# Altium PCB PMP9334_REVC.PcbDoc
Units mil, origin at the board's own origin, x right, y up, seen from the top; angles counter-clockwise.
Board outline 4400 x 1100 mil, 4 copper layers (Top Layer, Mid-Layer 1, Mid-Layer 2, Bottom Layer), stack 61.8 mil thick; 57 components, 29 nets, 127 pads, 87 vias.
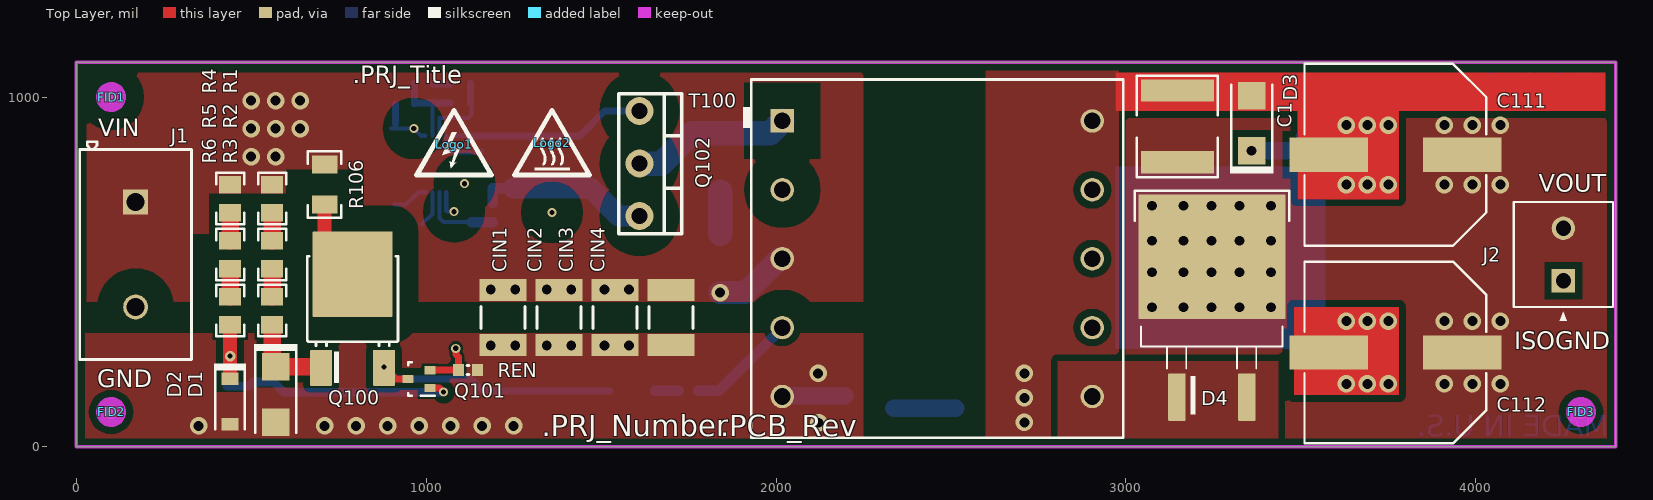
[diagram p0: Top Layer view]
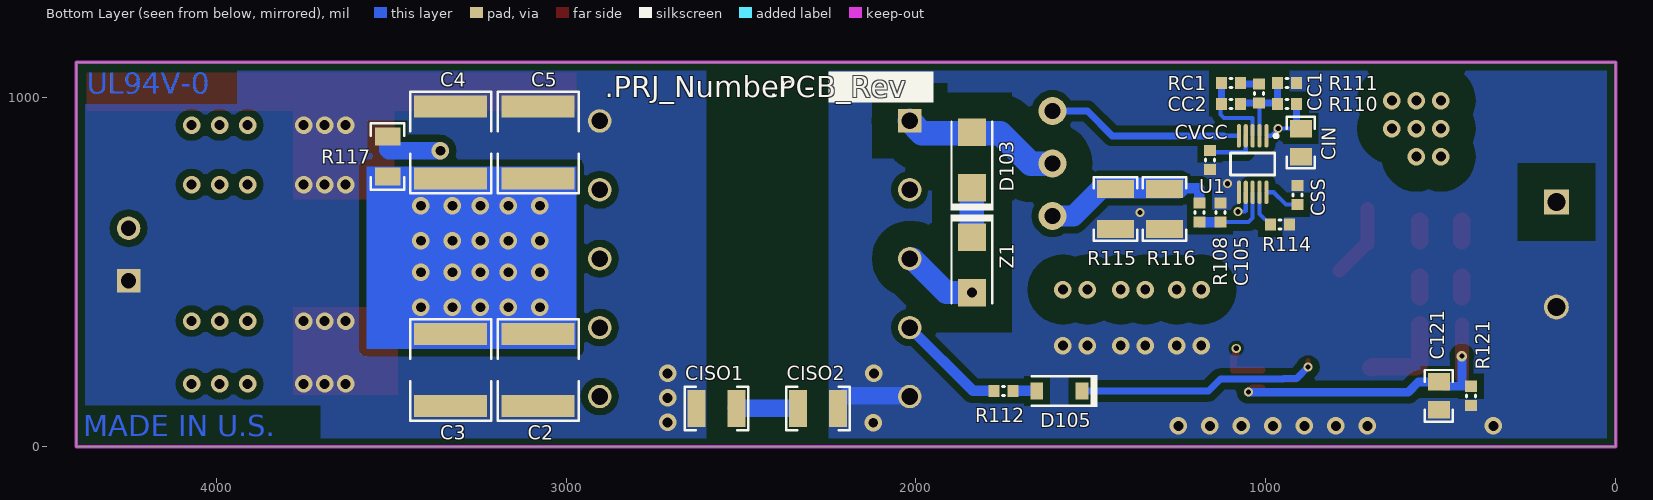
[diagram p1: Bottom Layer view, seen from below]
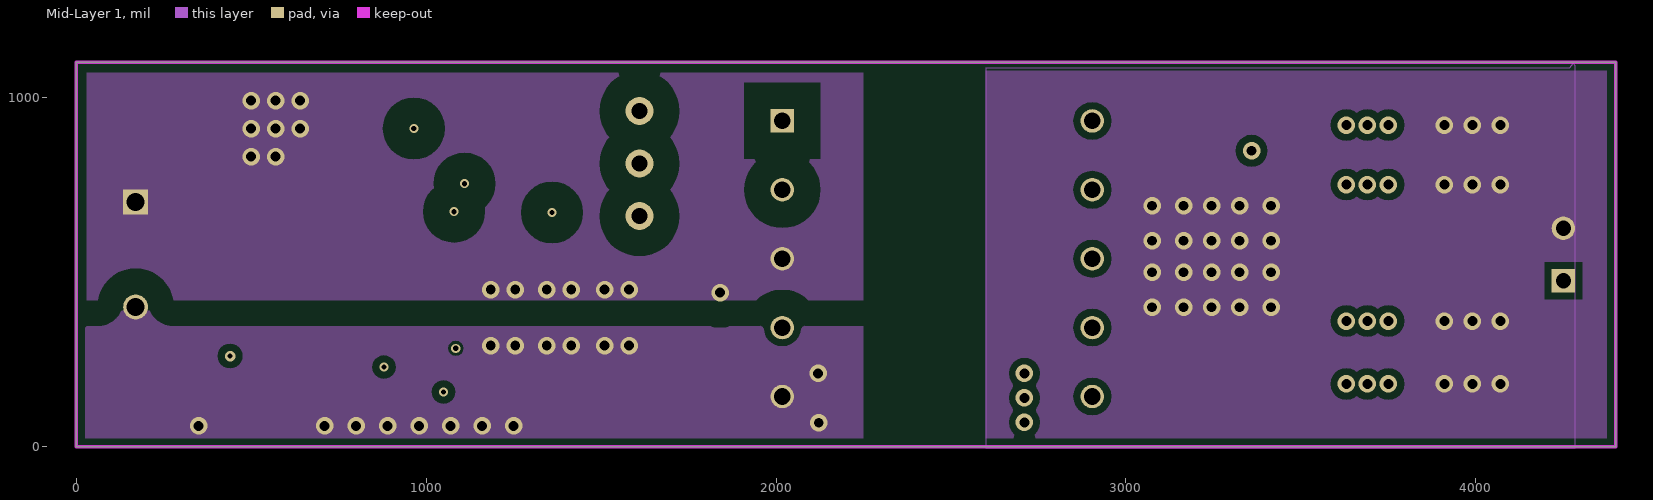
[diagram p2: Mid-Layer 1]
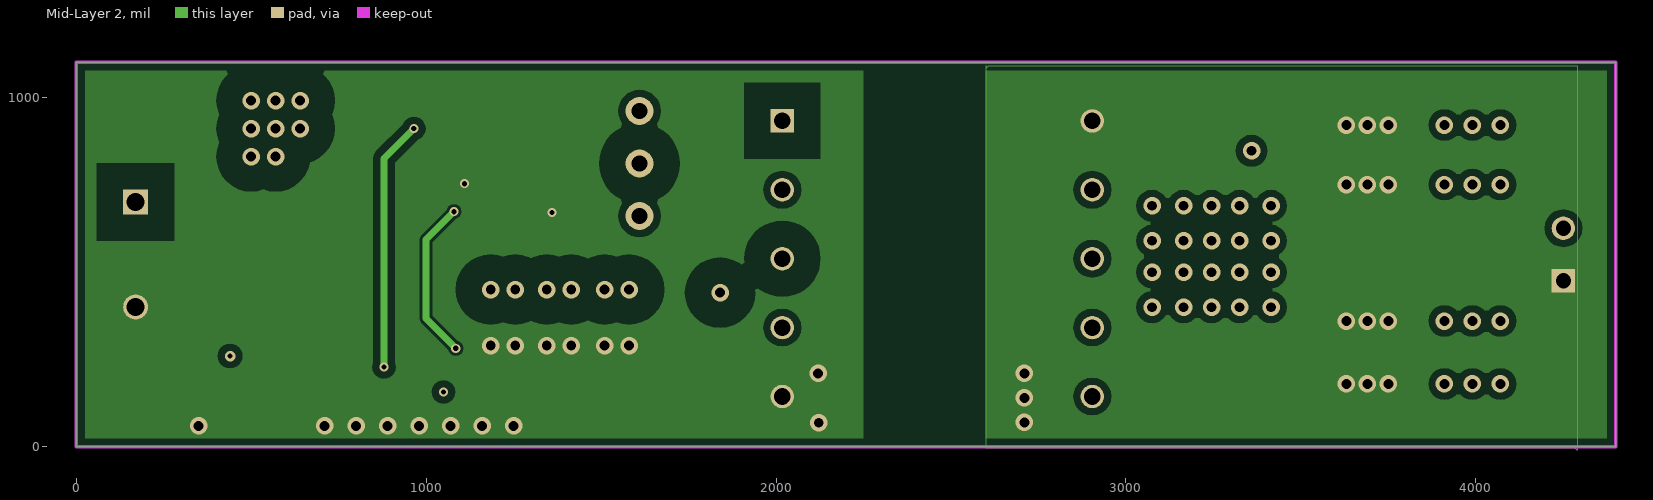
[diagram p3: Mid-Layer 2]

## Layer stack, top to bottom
Top Solder: solder mask 0.4, Solder Resist, Dk 3.5
Top Layer: signal copper 1.4
Dielectric1: prepreg 12.6, FR-4, Dk 4.2
Mid-Layer 1: signal copper 1.4
Dielectric2: core 31, FR-4, Dk 4.2
Mid-Layer 2: signal copper 1.4
Dielectric3: prepreg 12.6, FR-4, Dk 4.2
Bottom Layer: signal copper 1.4
Bottom Solder: solder mask 0.4, Solder Resist, Dk 3.5

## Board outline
0,0 4400,0 4400,1100 0,1100

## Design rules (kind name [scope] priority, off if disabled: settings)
AcuteAngle [All] p1: minimum=4.50000000000000E+0001 checktracksonly=FALSE
AssemblyTestPointUsage [All] p1: valid=2
Clearance Clearance_1206 [HasFootprint('1206') vs HasFootprint('1206')] p1: gap=60
Clearance Clearance_Keepouts [((IsTrack Or IsArc) And Not InPoly) And IsFree and IsKeepOut vs ((IsTrack Or IsArc) And Not InPoly) And IsFree and IsKeepOut] p2: gap=25
Clearance Clearance_SYNC [InNet('SYNC') vs InNet('CS') or InNet('SS')] p3: gap=7.8
Clearance Clearance_UVLO [InNet('UVLO') vs InNet('CS') or InNet('GND')] p4: gap=7.8
Clearance Clearance_CS [InNet('CS') vs InNet('UVLO') or InNet('SYNC')] p5: gap=7.8
Clearance Clearance_FB [InNet('FB') vs InNet('VIN IC') or InNet('COMP')] p6: gap=7.8
Clearance Clearance_COMP [InNet('COMP') vs InNet('FB') or InNet('VCC')] p7: gap=7.8
Clearance Clearance_VCC [InNet('VCC') vs InNet('COMP') or InNet('OUT')] p8: gap=7.8
Clearance Clearance_MUB10A-N [HasFootprint('MUB10A_N') vs HasFootprint('MUB10A_N')] p9: gap=8
Clearance Clearance_R4 [InNet('NetR4_1') vs InNet('VIN HV')] p10: gap=30
Clearance Clearance_R1 [InNet('VIN HV') vs InNet('NetR1_1')] p11: gap=30
Clearance Clearance_ISO [InNet('ISO') vs InNet('GND') or InNet('ISO GND')] p12: gap=60
Clearance Clearance_NMOS_DRAIN [InNet('VIN HV') vs InNet('NMOS DRAIN')] p13: gap=75
Clearance Clearance_TO220 [HasFootprint('TO220-3_A') vs HasFootprint('TO220-3_A')] p14: gap=70
Clearance Clearance_HV_KeepOut [InNetClass('HV') vs IsKeepOut] p15: gap=25
Clearance Clearance_HV [InNetClass('HV')] p16: gap=75
Clearance Clearance_Poly [InPolygon] p17: gap=20
Clearance Clearance_BoardEdge_MountingHoles [OnCopper and InComponentClass('Mounting Holes') vs IsKeepOut] p18: gap=40
Clearance Clearance_BoardEdge_Poly [OnCopper and (InPoly or IsRegion) vs IsKeepOut] p19: gap=25
Clearance Clearance_BoardEdge [OnCopper and Not InComponentClass('Logo') and not InComponentClass('FiducialMark') and not InRegion(1000,500,4000,800) and Not IsKeepout vs IsKeepOut] p20: gap=25
Clearance [All] p21: gap=7.87
ComponentClearance ComponentClearance_MountingHoles_FiducialMarks [InComponentClass('Mounting Holes') vs InComponentClass('FiducialMark')] p1: gap=50 collisioncheckmode=3 verticalgap=10 showdistances=FALSE
ComponentClearance ComponentClearance_Shunt [InComponentClass('Header') vs InComponentClass('Shunt')] p2: gap=0 collisioncheckmode=3 verticalgap=0 showdistances=FALSE
ComponentClearance ComponentClearance_Logo [InComponentClass('Logo')] p3: gap=50 collisioncheckmode=3 verticalgap=10 showdistances=FALSE
ComponentClearance ComponentClearance_ScrewToNut [(HasFootprint('NY PMS 440 0025 PH')) vs (HasFootprint('Keystone_1902C'))] p4: gap=5 collisioncheckmode=3 verticalgap=10 showdistances=FALSE
ComponentClearance ComponentClearance_MountingHoles [InComponentClass('Mounting Holes')] p5: gap=250 collisioncheckmode=3 verticalgap=100000 showdistances=FALSE
ComponentClearance ComponentClearance_SmallPassives [HasFootprint('0201*') or HasFootprint('0402*') or HasFootprint('0508') or HasFootprint('0603*') or HasFootprint('0612') or HasFootprint('0805*') or HasFootprint('0815*') or HasFootprint('0830*') or HasFootprint('1206*') or HasFootprint('1210*') or HasFootprint('1808*') or HasFootprint('1812*') or HasFootprint('1825*') or HasFootprint('2010*') or HasFootprint('2220*') or HasFootprint('2225*') or HasFootprint('2512*') or HasFootprint('2728*') or HasFootprint('3518*') vs HasFootprint('0201*') or HasFootprint('0402*') or HasFootprint('0508') or HasFootprint('0603*') or HasFootprint('0612') or HasFootprint('0805*') or HasFootprint('0815*') or HasFootprint('0830*') or HasFootprint('1206*') or HasFootprint('1210*') or HasFootprint('1808*') or HasFootprint('1812*') or HasFootprint('1825*') or HasFootprint('2010*') or HasFootprint('2220*') or HasFootprint('2225*') or HasFootprint('2512*') or HasFootprint('2728*') or HasFootprint('3518*')] p6: gap=20 collisioncheckmode=3 verticalgap=10 showdistances=FALSE
ComponentClearance ComponentClearance_THtoSMT [IsThruComponent vs IsSMTComponent] p7: gap=50 collisioncheckmode=3 verticalgap=30 showdistances=FALSE
ComponentClearance ComponentClearance_THtoTH [IsThruComponent vs IsThruComponent] p8: gap=50 collisioncheckmode=3 verticalgap=30 showdistances=FALSE
ComponentClearance [All] p9: gap=40 collisioncheckmode=3 verticalgap=10 showdistances=FALSE
DiffPairsRouting [All] p1: maxlimit=100 minlimit=10 mostfreqgap=10 toplayer_minwidth=15 toplayer_maxwidth=15 toplayer_prefwidth=15 midlayer1_minwidth=15 midlayer1_maxwidth=15 midlayer1_prefwidth=15 midlayer2_minwidth=15 midlayer2_maxwidth=15 midlayer2_prefwidth=15 bottomlayer_minwidth=15 bottomlayer_maxwidth=15 bottomlayer_prefwidth=15 maxuncoupledlength=1000
FabricationTestPointUsage TestPointUsage [All] p1: valid=2 allowmultiple=FALSE
FabricationTestpoint Testpoint [All] p1: side=3 testpointundercomponent=TRUE minsize=40 maxsize=100 preferedsize=60 minholesize=0 maxholesize=40 preferedholesize=32 testpointgrid=1 allowsidetop=TRUE allowsidebottom=TRUE usegrid=TRUE gridtolerance=0.01
FanoutControl Fanout_LCC [IsLCC] p1: bgadir=Out bgaviamode=Centered fanoutstyle=Auto fanoutdirection=Alternating viagrid=1 // Fanout_LCC (Default Rule)
FanoutControl Fanout_BGA [IsBGA] p2: bgadir=Out bgaviamode=Centered fanoutstyle=Auto fanoutdirection=Alternating viagrid=1 // Fanout_BGA (Default Rule)
FanoutControl Fanout_Default [All] p4: bgadir=Out bgaviamode=Centered fanoutstyle=Auto fanoutdirection=Alternating viagrid=1 // Fanout_Default (Default Rule)
FanoutControl Fanout_Small [(CompPinCount < 5)] p5: bgadir=Out bgaviamode=Centered fanoutstyle=Auto fanoutdirection=OutThenIn viagrid=1 // Fanout_Small (Default Rule)
Height [All] p1: minheight=0 maxheight=1500 prefheight=500
HoleSize [All] p1: absolutevalues=TRUE maxlimit=251 minlimit=8 maxpercent=80.000 minpercent=20.000
MinimumAnnularRing MinimumAnnularRing_ThermalPadVias [IsVia and InAnyComponent] p1: minimumring=5.91
MinimumAnnularRing [All] p2: minimumring=5
MinimumSolderMaskSliver MinimumSolderMaskSliver_Logo [InComponentClass('Logo') vs InComponentClass('Logo')] p1: minsoldermaskwidth=0.7
MinimumSolderMaskSliver [All] p2: minsoldermaskwidth=3.94
PlaneConnect [All] p1: planeconnectstyle=Direct reliefexpansion=10 reliefentries=4 reliefconductorwidth=10 reliefairgap=10
PolygonConnect [All] p1: connectstyle=Direct reliefconductorwidth=10 reliefentries=4 polygonreliefangle="90 Angle" airgapwidth=10
RoutingVias ThermalPadVias [IsVia and InAnyComponent] p1: holewidth=7.87 width=19.68 viastyle="Through Hole" minholewidth=7.87 minwidth=19.68 maxholewidth=12.99 maxwidth=23.62
RoutingVias [All] p2: holewidth=16 width=34 viastyle="Through Hole" minholewidth=7.87 minwidth=20 maxholewidth=40 maxwidth=65
SMDToCorner [All] p1: distance=4000
SilkToBoardRegionClearance [Not ((IsComment or IsDesignator) And (Hide <> 'False')) and not InRegion(1000,500,4000,800)] p1:
SilkToSilkClearance SilkToSilkClearance_Pb-FreeLogo [(HasFootprint('Pb-Free_Overlay_Medium') OR HasFootprint('Pb-Free_Overlay_Small')) vs (HasFootprint('Pb-Free_Overlay_Medium') OR HasFootprint('Pb-Free_Overlay_Small'))] p1: silktosilkclearance=0
SilkToSilkClearance [All] p2: silktosilkclearance=4
SilkToSolderMaskClearance SilkToComonentPadClearance [IsPad and InAnycomponent] p1: minsilkscreentomaskgap=5 clearancetoexposedcopper=TRUE
SilkToSolderMaskClearance "Silk to Solder Mask Opening" [All] p2: minsilkscreentomaskgap=4 clearancetoexposedcopper=FALSE
SilkToSolderMaskClearance SilkscreenOverComponentPads [IsPad] p3: minsilkscreentomaskgap=5 clearancetoexposedcopper=TRUE
SolderMaskExpansion [All] p1: expansion=1.97
UnpouredPolygon [All] p1: allowunpoured=FALSE
Width [All] p1: maxlimit=100 minlimit=6 preferedwidth=10 checkconnectedcopper=TRUE
13 further rules are at their usual default settings.

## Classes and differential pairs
component class FiducialMark: FID1 FID2 FID3
net class HV: "NMOS DRAIN" "PRI SW" "SNUB SW" "VIN HV"

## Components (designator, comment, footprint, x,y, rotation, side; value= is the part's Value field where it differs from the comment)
C1 "C5750X7S2A106M230KB" 2220_280 3147,916 r90 top
C2 "DNP" 2220_280 3080,220 r270 bottom
C3 "DNP" 2220_280 3330,220 r270 bottom
C4 "DNP" 2220_280 3330,870 r90 bottom
C5 "DNP" 2220_280 3080,870 r90 bottom
C105 "C0603C681K5RACTU" 0603L 1130,670 r90 bottom
C111 "EMVY350ATR471MKE0S" CAPSMT_62_KE0 3770,835 r180 top
C112 "EMVY350ATR471MKE0S" CAPSMT_62_KE0 3770,270 r180 top
C121 "GRM21BR71E334KA01L" 0805_HV 506,146 r270 bottom
CC1 "C0603C474K4RACTU" 0603L 1020,1010 r90 bottom
CC2 "C0603C331K5RACTU" 0603L 1100,980 r0 bottom
CIN "C2012X5R1E106K125AB" 0805_HV 900,870 r270 bottom
CIN1 "C1812V473KDRACTU" 1812 1220,370 r270 top
CIN2 "C1812V473KDRACTU" 1812 1380,370 r270 top
CIN3 "C1812V473KDRACTU" 1812 1540,370 r270 top
CIN4 "C1812V473KDRACTU" 1812 1700,370 r270 top
CISO1 "VJ1210A102JXGAT5Z" 1210 2570,110 r180 bottom
CISO2 "VJ1210A102JXGAT5Z" 1210 2280,110 r180 bottom
CSS "C0603C474K4RACTU" 0603L 910,720 r90 bottom
CVCC "GRM188R61E105KA12D" 0603L 1160,820 r270 bottom
D1 "CMZ5929B TR13" SMA 570,150 r270 top
D2 "MMSZ5231B-7-F" SOD-123 440,130 r270 top
D3 "CMZ5931B LEAD FREE" SMA 3359,925 r90 top
D4 "MBRB20200CTT4G" DDPAK 3245.55,388.31 r90 top
D103 "DNP" SMA 1840,820 r90 bottom
D105 "BAV21W-7-F" SOD-123 1590,160 r0 bottom
FID1 "Fiducial" Fiducial10-20 100,1000 r0 top
FID2 "Fiducial" Fiducial10-20 100,100 r0 top
FID3 "Fiducial" Fiducial10-20 4300,100 r0 top
J1 "1707027" Phoenix_1707027 170,550 r270 top
J2 "1727010" PhoenixConact_1727010 4250,550 r90 top
Logo1 "DANGER HIGH VOLTAGE" IEC_HighVoltage_Small 1080,865 r0 top
Logo2 "CAUTION HOT SURFACE" IEC_HotSurface_Small 1360,870 r0 top
Q100 "FQD2N100TM" DPAK 790,360 r90 top
Q101 "CMST2222A TR" SOT-323 979.32,194 r180 top
Q102 "STP8NK100Z" TO220-3_A 1610,810 r0 top
R1 "CRCW0805200KJNEA" 0805_HV 560,710 r90 top
R2 "CRCW0805200KJNEA" 0805_HV 560,550 r90 top
R3 "CRCW0805200KJNEA" 0805_HV 560,390 r90 top
R4 "CRCW08051M00JNEA" 0805_HV 440,710 r90 top
R5 "CRCW08051M00JNEA" 0805_HV 440,550 r90 top
R6 "CRCW08051M00JNEA" 0805_HV 440,390 r90 top
R106 "CRCW12064K99FKEA" 1206 710,750 r90 top
R108 "CRCW0603499RFKEA" 0603L 1190,670 r90 bottom
R110 "RG1608P-1872-B-T5" 0603L 940,980 r180 bottom
R111 "CRCW06031K50FKEA" 0603L 940,1040 r0 bottom
R112 "CRCW060316R0JNEA" 0603L 1750,160 r180 bottom
R114 "CRCW0603215KFKEA" 0603L 960,635.5 r0 bottom
R115 "MCR25JZHFLR510" 1210 1430,680 r90 bottom
R116 "MCR25JZHFLR510" 1210 1290,680 r90 bottom
R117 "CRCW1206100RFKEA" 1206 3510,830 r270 bottom
R121 "RC0603FR-07300KL" 0603L 414,146 r90 bottom
RC1 "CRCW06031K87FKEA" 0603L 1100,1040 r180 bottom
REN "RC0603FR-07300KL" 0603L 1120,220 r180 top
T100 "G094215LF" GCI_G094215LF 2461,538 r0 top locked
U1 "LM5022MM" MUB10A_N 1038,808.5 r270 bottom
Z1 "DNP" SMA 1840,520 r270 bottom

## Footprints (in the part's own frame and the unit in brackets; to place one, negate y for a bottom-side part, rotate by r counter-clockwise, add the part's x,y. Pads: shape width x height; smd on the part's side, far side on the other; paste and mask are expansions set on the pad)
0603L [mm] "0603 from SM-752 data"
  rect 0.8x0.85 smd: 1(-0.7,0) 2(0.7,0)
  silkscreen extent -0.07,-0.33 0.07,0.33, body extent -0.87,-0.47 0.87,0.47, height 0.85
0805_HV [mil] "0805 with 30mil clearance between pads"
  rect 50x63 smd: 1(-40,0) 2(40,0)
  silkscreen extent -74,-40 74,40, body extent -43,-29 43,29, height 43
1206 [mm] "1206 from SM-752 data"
  rect 1.3x1.85 smd: 1(-1.45,0) 2(1.45,0)
  silkscreen extent -2.4,-1.21 2.4,1.21, body extent -1.7,-0.9 1.7,0.9, height 1.35
1210 [mm] "1210 from SM-752 data"
  rect 1.3x2.7 smd: 1(-1.45,0) 2(1.45,0)
  silkscreen extent -2.32,-1.57 2.32,1.57, body extent -1.7,-1.35 1.7,1.35, height 1.35
1812 [mm]
  rect 1.6x3.4 smd: 1(-2,0) 2(2,0)
  silkscreen extent -0.8,-1.6 0.8,1.6, body extent -2.4,-1.7 2.4,1.7, height 1.35
2220_280 [mm] "Chip Capacitor, Body 5.7x5.0mm, IPC Medium Density"
  rect 1.6x5.3 smd: 1(-2.6,0) 2(2.6,0)
  silkscreen extent -3.69,-2.94 3.69,2.94, body extent -2.95,-2.62 2.95,2.62, height 2.8
CAPSMT_62_KE0 [mm] "12.5 x 13.5mm:  Chemi-Con KE0"
  rect 5.7x2.5 smd: 1(-4.85,0) 2(4.85,0)
  silkscreen extent -6.6,-6.6 6.6,6.6, body extent -6.6,-6.6 6.6,6.6, height 14
DDPAK [mil] "D2-PAK, 3-Pads, Body 9.7x10.4mm (max), TO-263AB, using Vishay Silionix recommended pad sizes"
  rrect8% 135x49.49 smd: 1(-246.06,100) 3(-246.06,-100)
  rrect1% 355x420 smd paste-181.1: 4(155.51,0)
  silkscreen extent -295,-220 344,220, body extent -295,-202 324,202, height 180
DPAK [mm] "D-PAK, 3-Pads, Body 6.22x6.73mm (max), TO-252AA using nominal STEP model"
  rrect6% 2.6x1.6 smd: 1(-3.4,2.28) 3(-3.4,-2.28)
  rrect2% 6.2x5.8 smd paste-2.9: 4(3.4,0)
  silkscreen extent -4.5,-3.3 4.7,3.28, body extent -3.86,-3.29 5.84,3.29, height 2.48
Fiducial10-20 [mm]
  round 1 smd mask+0.5: 1(0,0)
  Top Layer keep-out circle w1.178: c0,0 r0.5
GCI_G094215LF [mm] "TH, 10-Leads, Body 26x27mm, Pitch 5mm"
  rect 1.7x1.7 hole 1.2: 1(-11.25,10)
  round 1.7 hole 1.2: 2(-11.25,5) 3(-11.25,0) 4(-11.25,-5) 5(-11.25,-10) 6(11.25,-10) 7(11.25,-5) 8(11.25,0) 9(11.25,5) 10(11.25,10)
  silkscreen extent -14.1,-13 13.5,13, body extent -13.5,-13 13.5,13, height 16.52
IEC_HighVoltage_Small [mil]
  silkscreen extent -107,-88 107,97
IEC_HotSurface_Small [mil]
  silkscreen extent -107,-93 107,92
MUB10A_N [mm] "TSSOP, 10-Leads, Body 3x3mm, Pitch 0.5mm, IPC Medium Density"
  oval 1.7x0.3 smd: 1(-2.05,1) 2(-2.05,0.5) 3(-2.05,0) 4(-2.05,-0.5) 5(-2.05,-1) 6(2.05,-1) 7(2.05,-0.5) 8(2.05,0) 9(2.05,0.5) 10(2.05,1)
  silkscreen extent -2.17,-1.6 0.8,1.82, body extent -1.6,-1.6 1.6,1.6, height 1.09
Phoenix_1707027 [mm] "Terminal Block, 7.62mm, 2 Pos, TH"
  rect 1.8x1.8 hole 1.3: 1(-3.81,0)
  round 1.8 hole 1.3: 2(3.81,0)
  silkscreen extent -8.19,-4.05 7.62,4.05, body extent -8.19,-4.05 7.62,4.05, height 10
PhoenixConact_1727010 [mm]
  rect 1.7x1.7 hole 1.1: 1(-1.905,0)
  round 1.7 hole 1.1: 2(1.905,0)
  silkscreen extent -4.8,-3.6 3.81,3.6, body extent -3.81,-3.6 3.81,3.7, height 8.52
SMA [mm] "Molded Diode, 2-Leads, Body 4.3x2.6mm, IPC Medium Density, based on OnSemi component dimensions and land pattern"
  rect 2x2 smd: 1(-2,0) 2(2,0)
  silkscreen extent -3.66,-1.57 2.79,1.57, body extent -2.6,-1.3 2.6,1.3, height 2.42
SOD-123 [mm] "On Semi recommended land pattern"
  rect 0.915x1.22 smd: 1(-1.637,0) 2(1.637,0)
  silkscreen extent -2.74,-1.17 2.03,1.17, body extent -1.93,-0.9 1.93,0.9, height 1.35
SOT-323 [mm] "Zetex recommended land pattern.  March 2007"
  rect 0.8x0.6 smd: 1(-0.8,0.65) 2(-0.8,-0.65) 3(0.8,0)
  silkscreen extent -1.14,-1.22 0.77,1.22, body extent -1.13,-1.13 1.12,1.12, height 1.13
TO220-3_A [mil]
  round 80 hole 45: 1(0,150) 2(0,0) 3(0,-150)
  silkscreen extent -60,-200 120,200

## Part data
C1: "CAP, CERM, 10 µF, 100 V, +/- 20%, X7S, 2220"
C2 C3 C4 C5: library part C5750X7S2A106M230KB, "CAP, CERM, 10 µF, 100 V, +/- 20%, X7S, 2220"
C105: "CAP, CERM, 680 pF, 50 V, +/- 10%, X7R, 0603"
C111 C112: "CAP, AL, 470 µF, 35 V, +/- 20%, 0.07 ohm, SMD"
C121: "CAP, CERM, 0.33 µF, 25 V, +/- 10%, X7R, 0805"
CC1 CSS: "CAP, CERM, 0.47 µF, 16 V, +/- 10%, X7R, 0603"
CC2: "CAP, CERM, 330 pF, 50 V, +/- 10%, X7R, 0603"
CIN: "CAP, CERM, 10 µF, 25 V, +/- 10%, X5R, 0805"
CIN1 CIN2 CIN3 CIN4: "CAP, CERM, 0.047 µF, 1000 V, +/- 10%, X7R, 1812"
CISO1 CISO2: "CAP, CERM, 1000 pF, 1000 V, +/- 5%, C0G/NP0, 1210"
CVCC: "CAP, CERM, 1 µF, 25 V, +/- 10%, X5R, 0603"
D1: "Diode, Zener, 15 V, 1.5 W, SMA"
D2: "Diode, Zener, 5.1 V, 500 mW, SOD-123"
D3: "Diode, Zener, 18 V, 900 mW, SMA"
D4: "Diode, Schottky, 200 V, 20 A, DDPAK"
D103: library part STTH112A, "Diode, Ultrafast, 1200 V, 1 A, SMA"
D105: "Diode, Switching, 200 V, 0.2 A, SOD-123"
FID1 FID2 FID3: "Fiducial mark.  There is nothing to buy or mount."
J1: "Terminal Block, 7.62mm, 2 Pos, TH"
J2: "Conn Term Block, 2POS, 3.81mm, TH"
Logo1: library part IEC_HighVoltage, "IEC 61010-1 High Voltage Warning"
Logo2: library part IEC_HotSurface, "IEC 61010-1 Hot Surface Warning"
Q100: "MOSFET, N-CH, 1000 V, 1.6 A, DPAK"
Q101: library part "CMST2222A TR, Central Semiconductor", "Transistor, NPN, 40 V, 0.6 A, SOT-323"
Q102: "MOSFET, N-CH, 1000 V, 6.5 A, TO-220AB"
R1 R2 R3: "RES, 200 k, 5%, 0.125 W, 0805"
R4 R5 R6: "RES, 1.0 M, 5%, 0.125 W, 0805"
R106: "RES, 4.99 k, 1%, 0.25 W, 1206"
R108: "RES, 499, 1%, 0.1 W, 0603"
R110: "RES, 18.7 k, 0.1%, 0.1 W, 0603"
R111: "RES, 1.50 k, 1%, 0.1 W, 0603"
R112: "RES, 16, 5%, 0.1 W, 0603"
R114: library part CRCW0603215kFKEA, "RES, 215 k, 1%, 0.1 W, 0603"
R115 R116: "RES, 0.51, 1%, 0.5 W, 1210"
R117: "RES, 100, 1%, 0.25 W, 1206"
R121 REN: "RES, 300 k, 1%, 0.1 W, 0603"
RC1: "RES, 1.87 k, 1%, 0.1 W, 0603"
T100: "Transformer, 3 mH, TH"
U1: "60V Low Side Controller for Boost and SEPIC, 10-pin MSOP"
Z1: library part SMAJ250A, "Diode, TVS, Uni, 250 V, 400 W, SMA"

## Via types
v1: diameter 50, hole 28, Top Layer to Bottom Layer, tented both sides, 79 vias
v2: diameter 26, hole 15, Top Layer to Bottom Layer, tented both sides, 7 vias
v3: diameter 30, hole 15, Top Layer to Bottom Layer, tented both sides, 1 vias

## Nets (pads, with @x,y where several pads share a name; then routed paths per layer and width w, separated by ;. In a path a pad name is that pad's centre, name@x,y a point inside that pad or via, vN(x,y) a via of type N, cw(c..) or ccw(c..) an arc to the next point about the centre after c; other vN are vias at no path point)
ANODE: D105.2 R112.2 | length 68
  Bottom Layer w30: D105.2 R112.2
"AUX SW": R112.1 T100.4 | length 315.6
  Bottom Layer w30: R112.1 1836.94,160 T100.4
COMP: CC2.2 RC1.1 U1.3 | length 242.1
  Bottom Layer w11.8: U1.3 1038,940.5 1098,940.5 1098.5,940 1120,940 1130,950 1130,977.56 CC2.2 ; RC1.1 RC1.1@1130,1037.56
  Bottom Layer w20: CC2.2 RC1.1
CS: C105.1 R108.1 U1.8 | length 230.3
  Bottom Layer w11.8: U1.8 1038,654.5 1050,642.5 C105.1@1129.94,642.5
  Bottom Layer w30: C105.1@1129.94,642.5 C105.1 R108.1
FB: CC1.1 CC2.1 R110.1 R111.2 U1.2 | length 260.8
  Bottom Layer w11.8: U1.2 1018.31,980.76 CC1.1 ; CC2.1@1070,982.44 CC2.1
  Bottom Layer w20: R111.2 R110.1 970,982.44 CC1.1 CC2.1@1070,982.44
GND: C105.2 C121.2 CIN1.2 CIN2.2 CIN3.2 CIN4.2 CIN.2 CISO2.2 CSS.2 CVCC.2 D1.2 D2.2 J1.2 R111.1 R114.1 R115.1 R116.1 R121.1 REN.1 T100.5 U1.6 | length 176.5
  Bottom Layer w50: T100.5@2019.79,146 2196.32,146
  other v1: 350,60 710,60 800,60 890,60 980,60 1070,60 1160,60 1250,60 2122,69 2120,210 1185,290 1255,290 1345,290 1415,290 1510,290 1580,290
  other v2: 1360,670 1110,752.5
ISO: CISO1.2 CISO2.1 | length 175.8
  Bottom Layer w50: CISO2.1 CISO1.2
"ISO GND": C1.2 C2.2 C3.2 C4.2 C5.2 C111.2 C112.2 CISO1.1 D3.2 J2.1 T100.10
  other v1: 2710,70 2710,140 3630,180 3690,180 3750,180 2710,210 3630,360 3690,360 3750,360 3630,750 3690,750 3750,750 3630,920 3690,920 3750,920
NetCC1_2: CC1.2 RC1.2 | length 53.5
  Bottom Layer w11.8: RC1.2@1070,1037.56 RC1.2
  Bottom Layer w20: CC1.2 RC1.2@1070,1037.56
NetD3_1: D3.1 R117.1 | length 189.6
  Bottom Layer w50: v1(3359,846.26) 3506.26,846.26 3510,850 R117.1
NetD4_1: D4.1 D4.3 T100.6
NetR1_1: R1.1 R2.2 | length 54.6
  Top Layer w50: R2.2 560,644.6
NetR2_1: R2.1 R3.2 | length 54.6
  Top Layer w50: R3.2 560,484.6
NetR4_1: R4.1 R5.2 | length 54.6
  Top Layer w50: R5.2 440,644.6
NetR5_1: R5.1 R6.2 | length 54.6
  Top Layer w50: R6.2 440,484.6
"NMOS DRAIN": Q100.4 R106.1 | length 213.1
  Top Layer w40: Q100.4@710,580 R106.1@710,680 ; Q100.4@710,583.86 Q100.4@790,503.86
"NMOS GATE": D1.1 Q100.1 R3.1 | length 256.7
  Top Layer w50: R3.1 560,238.74 D1.1 697.64,228.74 Q100.1
"NPN BASE": C121.1 D2.1 Q101.1 R6.1 R121.2 | length 916.3
  Top Layer w20: Q101.1 1038.73,168.41 v2(1049.92,157.22)
  Top Layer w40: D2.1@440,200 v3(440,260) R6.1
  Bottom Layer w25: 431.13,173.56 440,173.56 ; v3(440,260) 440,173.56 ; v2(1049.92,157.22) 593.4,156.6 564,186 C121.1 493.56,173.56 440,173.56
OUT: Q102.1 U1.5 | length 562
  Bottom Layer w11.8: U1.5 1119.21,889.21
  Bottom Layer w20: 1119.21,889.21 1439.21,889.21 1510,960 Q102.1
"PRI SW": D103.2 Q102.2 T100.1 | length 458.5
  Bottom Layer w70: Q102.2 1672.13,810 1759.14,897.01 1840,897.01 1983.39,897.01 T100.1
"SNUB SW": D103.1 Z1.1 | length 121.3
  Bottom Layer w70: Z1.1@1840,608.74 D103.1@1840,730
SOURCE: Q102.3 R108.2 R115.2 R116.2 | length 462
  Bottom Layer w30: R108.2 1190,740 1236.45,740
  Bottom Layer w60: R116.2@1250,740 1470,740 1550,660 Q102.3@1590,660
SS: CSS.1 U1.10 | length 103.3
  Bottom Layer w11.8: CSS.1 942.44,692.44 977.8,727.8 U1.10
SYNC: R114.2 U1.9 | length 104.6
  Bottom Layer w11.8: R114.2 1018,665.95 ; 1018.31,666.26 U1.9
UVLO: Q101.2 REN.2 U1.7 | length 682.6
  Top Layer w20: Q101.2 REN.2@1091.95,220 ; v2(1085,282) 1085,265 1092.44,257.56 REN.2
  Mid-Layer 1 w11.8: v2@1079.1,671.6 v2(1080,672.5)
  Mid-Layer 2 w20: v2(1080,672.5) 1000,592.5 1000,367 v2(1085,282)
  Bottom Layer w11.8: U1.7 1057.68,674.82 1060,672.5 v2(1080,672.5)
VCC: CVCC.1 U1.4 | length 151.8
  Bottom Layer w11.8: U1.4 1057.76,889.21 1057.76,842.05 1154.49,842.05 CVCC.1
"VIN HV": CIN1.1 CIN2.1 CIN3.1 CIN4.1 J1.1 R1.2 R4.2 R106.2 T100.3 Z1.2 | length 218.2
  Bottom Layer w65: v1(1840,441.26) 1913.29,441.26 2010.03,538 T100.3
  other v1: 1185,450 1255,450 1345,450 1415,450 1510,450 1580,450 500,830 570,830 500,910 570,910 640,910 500,990 570,990 640,990
"VIN IC": CIN.1 D105.1 Q100.3 Q101.3 R110.2 U1.1 | length 1656.1
  Top Layer w15: v2(879.76,228.24) Q100.3@879.76,246.14
  Top Layer w20: v2(879.76,228.24) 914,194 Q101.3
  Mid-Layer 2 w20: v2(879.76,228.24) 879.76,824.6 v2(965.17,910)
  Bottom Layer w11.8: CIN.1 v2(965.17,910) 985.95,889.21 U1.1
  Bottom Layer w20: v2(879.76,228.24) 913,195 950,195 950.34,194.66 1130,194.66 1164.66,160 D105.1 ; CIN.1@912.44,922.44 R110.2
VOUT: C1.1 C2.1 C3.1 C4.1 C5.1 C111.1 C112.1 D4.4 J2.2 R117.2
  other v1: 3910,180 3990,180 4070,180 3910,360 3990,360 4070,360 3074.55,399.31 3164.55,399.31 3244.55,399.31 3324.55,399.31 3414.55,399.31 3074.55,499.31 3164.55,499.31 3244.55,499.31 3324.55,499.31 3414.55,499.31 3074.55,589.31 3164.55,589.31 3244.55,589.31 3324.55,589.31 3414.55,589.31 3074.55,689.31 3164.55,689.31 3244.55,689.31 3324.55,689.31 3414.55,689.31 3910,750 3990,750 4070,750 3910,920 3990,920 4070,920
pads on no net: FID1.1 FID2.1 FID3.1 T100.2 T100.7 T100.8 T100.9

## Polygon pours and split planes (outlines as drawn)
no net on Mid-Layer 2 "ISO GND" (solid, shelved, pour order 32): 2602.33,1083.92 2607.86,1090 4290,1090 4290,-10 4283.63,-3 2601.16,-3 2601.16,1090
GND on Mid-Layer 2 "GND" (solid, pour order 29): 0,1100 2250,1100 2250,0 0,0
"ISO GND" on Mid-Layer 2 "ISO GND" (solid, pour order 31): 2600,1100 4400,1100 4400,0 2600,0
no net on Mid-Layer 1 "MidLayer1-VOUT" (solid, shelved, pour order 24): 2602.33,1083.92 4267.46,1083.92 4278.45,1096 4283,1091 4283,-3 2601.16,-3 2601.16,1083.79
VOUT on Mid-Layer 1 "MidLayer1-VOUT" (solid, pour order 23): 2600,1100 4400,1100 4400,0 2600,0
"VIN HV" on Mid-Layer 1 "Mid Layer-VIN" (solid, remove dead copper, pour order 25): 0,1100 2250,1100 2250,420 0,420 0,1100
GND on Mid-Layer 1 "Mid Layer-GND" (solid, remove dead copper, pour order 27): 0,0 0,390 2250,390 2250,0 0,0
"ISO GND" on Bottom Layer "L4 RTN" (solid, pour order 34): 2600,1100 4400,1100 4400,0 2600,0
GND on Bottom Layer "L4 gnd" (solid, remove dead copper, pour order 33): 0,1100 2250,1100 2250,0 0,0
NetD4_1 on Top Layer "Top Layer-D4" (solid, remove dead copper, pour order 18): 2805,245 3435,245 3435,0 2805,0 2805,245
"ISO GND" on Top Layer "L1 RTN" (solid, pour order 21): 2600,1100 2980,1100 2980,0 2600,0
VOUT on Top Layer "L1 out" (solid, pour order 19): 3000,940 4400,940 4400,0 3000,0
GND on Top Layer "Top Layer-GND" (solid, remove dead copper, pour order 22): 0,0 0,325 2250,325 2250,0
"VIN HV" on Top Layer "Top Layer-VIN" (solid, remove dead copper, pour order 20): 0,1100 2250,1100 2250,415 0,415

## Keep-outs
Keep-Out Layer:
  the board outline again, w10
  text ".Layer_Name" at -133,-1868.49 h60

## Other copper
Top Layer:
  rectangle net "ISO GND": 3480,147.91 3780,400
  rectangle net "ISO GND": 3490,707.91 3780,960
  rectangle net "ISO GND": 2970,960 4370,1070
  text ".Layer_Name" at -133,-1868.49 h60
Bottom Layer:
  rectangle net VOUT: 2970,280 3570,800.87
  text "UL94V-0" at 4370,1010 h60
  text "MADE IN U.S." at 4380,30 h60
  text ".Layer_Name" at -133,-1868.49 h60

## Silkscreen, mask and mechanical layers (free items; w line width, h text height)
Top Overlay:
  text ".PRJ_Title" at 790,1040 h50
  text "VIN" at 63.46,887.55 h50
  text "VOUT" at 4180,730 h50
  text "ISOGND" at 4110,280 h50
  text "GND" at 60,170 h50
  text ".PRJ_Number" at 1330,30 h60
  text ".PCB_Rev" at 1840,30 h60
  text ".Layer_Name" at -133,-1868.49 h60
Bottom Overlay:
  rectangle: 1950,985 2250,1073
  text "-" at 2320,1000 h60
  text ".PCB_Rev" at 2420,1000 h60
  text ".PRJ_Number" at 2890,1000 h60
  text ".Layer_Name" at -133,-1868.49 h60
Top Paste:
  text ".Layer_Name" at -133,-1868.49 h60
Bottom Paste:
  text ".Layer_Name" at -133,-1868.49 h60
Top Solder:
  text ".Layer_Name" at -133,-1868.49 h60
  text ".Layer_Name" at -133,-1868.49 h60
Bottom Solder:
  text ".Layer_Name" at -133,-1868.49 h60
Drill Guide:
  text ".Layer_Name" at -133,-1868.49 h60
M1 Board Outline:
  the board outline again, w10
  text ".Layer_Name" at -133,-1868.49 h60
M2 Board Dimensions:
  rectangle: -585,-1410 -210,-1285
  rectangle: -710,-1285 -585,-1160
  lines w7: -710,-1285 290,-1285 ; -585,-1410 -585,-1160 ; -460,-1410 -460,-1160 ; -210,-1410 -210,-1160 ; 40,-1410 40,-1160 ; -710,-1410 -710,-1160 290,-1160 290,-1410 -710,-1410
  lines w10: -140,60 -120,0 ; -140,1040 -120,1100 ; -130,0 -110,0 ; -130,1100 -110,1100 ; -120,279.08 -120,0 ; -120,820.92 -120,1100 ; -100,60 -120,0 ; -100,1040 -120,1100
  text "1100 (mil)" at -84.01,289.08 h60 r90
  text ".Layer_Name" at -133,-1868.49 h60
M3 3D STEP Top:
  text ".Layer_Name" at -133,-1868.49 h60
M4 3D STEP Bottom:
  text ".Layer_Name" at -133,-1868.49 h60
M5 Assembly Top:
  lines w10: -1002,-1940.17 5598,-1940.17 ; -1002,-1736.83 5600,-1736.83 ; -1002,-1533.5 -1002,-2143.5 3003,-2143.5 5600,-2143.5 5600,-1533.5 -1001.5,-1533.5 -1001.5,-2143.5 574,-2143.5 ; 1463,-2143.5 1463,-1533.5 ; 2730,-1736.83 2730,-1533.5 ; 3570,-1736.83 3570,-1533.5 ; 4192,-2150 4192,-1947.17
  text "COMPONENTS MARKED 'DNP' SHOULD NOT BE POPULATED." at 443.5,-1328.5 h60
  text "ASSEMBLY VARIANT:" at 443,-1444 h60
  text ".VariantName" at 1479,-1444 h60
  text "PCB VIEWED FROM TOP SIDE" at -938.5,-1665.67 h60
  text "BOARD #:" at 1538,-1665.67 h60
  text ".PRJ_Number" at 2083.5,-1665.67 h60
  text "REV:" at 2928,-1665.67 h60
  text ".PCB_Rev" at 3219.5,-1665.67 h60
  text "SVN REV:" at 3766,-1665.67 h60
  text ".VersionControl_RevNumber" at 4272,-1665.67 h60
  text "TID #:" at 1538,-1869 h60
  text ".TID" at 2083.5,-1869 h60
  text "PLOT NAME =" at -938.5,-2074.34 h60
  text ".plot_File_Name" at -133,-2074.34 h60
  text "GENERATED    :" at 1540,-2074.34 h60
  text ".Print_Date" at 2409.5,-2074.34 h60
  text ".Print_Time" at 3138.5,-2074.34 h60
  text "TEXAS INSTRUMENTS" at 4403,-2074.34 h60
M6 Assembly Bottom:
  lines w10: -1002.5,-1737.33 5599.5,-1737.33 ; -1000.5,-1940.67 5599.5,-1940.67 ; 405.5,-2150.5 405.5,-1947.67 ; 1027.5,-1737.33 1027.5,-1534 ; 1867.5,-1737.33 1867.5,-1534 ; 3134.5,-2144 3134.5,-1534 ; 4023.5,-2144 5599,-2144 5599,-1534 -1002.5,-1534 -1002.5,-2144 1594.5,-2144 5599.5,-2144 5599.5,-1534
  text "COMPONENTS MARKED 'DNP' SHOULD NOT BE POPULATED." at 5392,-1328 h60
  text ".VariantName" at 4348,-1444 h60
  text "ASSEMBLY VARIANT:" at 5387,-1444 h60
  text ".VersionControl_RevNumber" at 325.5,-1666.17 h60
  text "SVN REV:" at 831.5,-1666.17 h60
  text ".PCB_Rev" at 1378,-1666.17 h60
  text "REV:" at 1669.5,-1666.17 h60
  text ".PRJ_Number" at 2514,-1666.17 h60
  text "BOARD #:" at 3059.5,-1666.17 h60
  text "PCB VIEWED FROM BOTTOM SIDE" at 5536,-1666.17 h60
  text ".TID" at 2514,-1869.5 h60
  text "TID #:" at 3059.5,-1869.5 h60
  text "TEXAS INSTRUMENTS" at 194.5,-2074.84 h60
  text ".Print_Time" at 1459,-2074.84 h60
  text ".Print_Date" at 2188,-2074.84 h60
  text "GENERATED    :" at 3057.5,-2074.84 h60
  text ".plot_File_Name" at 4730.5,-2074.84 h60
  text "PLOT NAME =" at 5536,-2074.84 h60
M9 Title Sheet:
  drawing of 57 lines, arcs and shapes, not listed
  text "1" at 29.84,7026.5 h70
  text "2" at 2525.5,7026.5 h70
  text "3" at 5014.84,7026.5 h70
  text "4" at 7521.51,7026.5 h70
  text "5" at 10020.5,7026.5 h70
  text "6" at 12525.5,7026.5 h70
  text "A" at -1126.5,5883.5 h70
  text "A" at 13673.5,5883.5 h70
  text "B" at -1126.5,3503.5 h70
  text "B" at 13673.5,3503.5 h70
  text "C" at -1126.5,1128.5 h70
  text "C" at 13673.5,1128.5 h70
  text "PROJECT TITLE:" at 10633.5,-732.5 h45
  text ".PRJ_Title" at 10683.5,-865.83 h70
  text "DESIGNED FOR:" at 10633.5,-1033.5 h45
  text ".PRJ_Customer" at 10683.5,-1173.5 h70
  text "D" at -1126.5,-1241.5 h70
  text "D" at 13673.5,-1241.5 h70
  text "FILE NAME:" at 10633.5,-1333.5 h45
  text ".PCB_File_Name_No_Path" at 10683.5,-1453.5 h70
  text "Texas Instruments (TI) and/or its licensors do not warrant the accuracy or completeness of this specification" at 5664,-1615.34 h45
  text "ENGINEER:" at 10633.5,-1623.5 h45
  text "LAYOUT BY:" at 12138.5,-1623.5 h45
  text "or any information contained therein. TI and/or its licensors do not warrant that this design will meet" at 5619.01,-1728 h45
  text ".PRJ_Engineer" at 10683.5,-1778.49 h70
  text ".PCB_Layout" at 12189,-1778.49 h70
  text "the specifications, will be suitable for your application or fit for any particular purpose, or will operate in" at 5619.01,-1840.67 h45
  text ".Layer_Name" at -133,-1868.49 h60
  text "ALTIUM DESIGNER VERSION:" at 12138.5,-1933.5 h45
  text "an implementation. TI and/or its licensors do not warrant that the design is production worthy. You should" at 5619.01,-1953.33 h45
  text "completely validate and test your design implementation to confirm the system functionality for your application." at 5664,-2066 h45
  text ".print_Scale" at 10683.5,-2066.83 h70
  text ".Application_BuildNumber" at 12189,-2066.83 h70
  text "1" at 29.84,-2273.5 h70
  text "2" at 2525.5,-2273.5 h70
  text "3" at 5014.84,-2273.5 h70
  text "4" at 7521.51,-2273.5 h70
  text "5" at 10020.5,-2273.5 h70
  text "6" at 12525.5,-2273.5 h70
M10 Fab Notes:
  drawing of 173 lines, arcs and shapes, not listed
  text "DESIGN INFORMATION" at 11667.02,5191 h60
  text "MIN. TRACK WIDTH:" at 11022.46,5011 h60
  text "8" at 12118.7,5011 h60
  text "MIL" at 12273.46,5011 h60
  text "MIN. CLEARANCE:" at 11022.46,4879 h60
  text "0.2" at 12058.7,4879 h60
  text "mm" at 12273.46,4879 h60
  text "MIN. VIA PAD SIZE:" at 11022.46,4747 h60
  text "24" at 12088.71,4747 h60
  text "MIL" at 12273.46,4747 h60
  text "0.05mm (2MIL)" at 11717.46,4605.29 h60
  text "MINIMUM ANNULAR RING" at 10693.23,4601 h60
  text "EXTERNAL" at 12425.46,4601 h60
  text "PER" at 10893.23,4483 h60
  text "IPC-D-275 CLASS 2 LEVEL C" at 11113.23,4483 h60
  text "MIL, HOLES" at 12601.46,4370.71 h60
  text "+/-" at 12209,4370 h60
  text "+/-" at 13063,4370 h60
  text "REGISTRATION TOLERANCES:" at 10693.23,4365 h60
  text "METAL" at 11893,4365 h60
  text "5" at 12469.2,4365 h60
  text "3" at 13302.2,4365 h60
  text "MIL" at 13418.46,4365 h60
  text "+/-" at 13063,4252 h60
  text "HOLE SIZE TOLERANCE (UNLESS OTHERWISE SPECIFIED):" at 10693.23,4247 h60
  text "3" at 13302.2,4247 h60
  text "MIL" at 13418.46,4247 h60
  text "MATERIAL:" at 10618.46,4037.54 h60
  text "FR-4 High Tg" at 11604.9,3897.21 h60
  text "FR-408" at 11039.46,3888.64 h60
  text "OTHER" at 12527.46,3888.64 h60
  text "X" at 11450,3880 h60
  text "62 MIL (1.6mm) +/-10%" at 11359.56,3725.92 h60
  text "THICKNESS:" at 10693.23,3721.64 h60
  text "X" at 11231.4,3721.64 h60
  text "OTHER" at 12644.46,3721.64 h60
  text "TOLERANCE:" at 10693.23,3563.64 h60
  text "X" at 11532.53,3563.64 h60
  text "ANSI IPC-6012 TYPE 3 CLASS 2" at 11719.48,3563.64 h60
  text "OTHER +/-" at 11719.46,3407.64 h60
  text "BOW & TWIST:" at 10693.23,3250.64 h60
  text "X" at 11532.53,3250.64 h60
  text "ANSI IPC-6012 TYPE 3 CLASS 2" at 11719.48,3250.64 h60
  text "OTHER +/-" at 11719.46,3092.13 h60
  text "DRILLING:" at 10618.46,2953.64 h60
  text "REFERENCE:" at 10693.23,2836.64 h60
  text "X" at 11341.46,2836.64 h60
  text "AS SHOWN" at 11528.46,2836.64 h60
  text "X" at 12242.46,2836.64 h60
  text "NC_DRILL FILES" at 12379.46,2836.64 h60
  text "PTH COPPER THICKNESS:" at 10693.23,2678.64 h60
  text "X" at 11823.46,2678.64 h60
  text "20-30 um" at 11960.46,2678.64 h60
  text "OTHER" at 12677.46,2678.64 h60
  text "BOARD FINISH:" at 10618.46,2519.64 h60
  text "SILKSCREEN:" at 10773.68,2401.64 h60
  text "X" at 11722.46,2401.64 h60
  text "TOP" at 11848.46,2401.64 h60
  text "X" at 12232.46,2401.64 h60
  text "BOTTOM" at 12359.46,2401.64 h60
  text "SILKSCREEN COLOR:" at 10773.68,2234.64 h60
  text "X" at 11721.42,2234.64 h60
  text "WHITE" at 11848.46,2234.64 h60
  text "OTHER" at 12359.46,2234.64 h60
  text "X" at 11852.42,2075.44 h60
  text "GREEN" at 11979.46,2075.44 h60
  text "OTHER" at 12597.46,2075.44 h60
  text "SOLDER RESIST COLOR:" at 10773.68,2064.64 h60
  text "X" at 11852.42,1905.44 h60
  text "MATTE" at 11979.46,1905.44 h60
  text "SEMI-GLOSS" at 12597,1904.8 h60
  text "IMMERSION GOLD (ENIG)" at 11679.46,1716.92 h60
  text "ENEPIG" at 13017,1713.64 h60
  text "SURFACE FINISH:" at 10618.46,1712.64 h60
  text "X" at 11492.51,1712.64 h60
  text "IMM. TIN/SILVER OR EQUIV" at 10948,1555.64 h60
  text "OTHER" at 12379.46,1555.64 h60
  text "ARRAY/PANEL:" at 10618.46,1376.64 h60
  text "CUT AND TRIM PER M1 BOARD OUTLINE" at 11679.46,1372.35 h60
  text "X" at 11490,1370 h60
  text "N.C. ROUTE" at 11679.46,1220.64 h60
  text "V. SCORE" at 12545.46,1220.64 h60
  text "CERTIFICATION:" at 10618.46,1083.64 h60
  text "MATERIALS AND WORKMANSHIP FOR ALL PCBS" at 11343.46,1083.64 h60
  text "TO MEET OR EXCEED THE REQUIREMENTS OF:" at 11343.46,985.64 h60
  text "X" at 10969.96,849.13 h60
  text "ANSI IPC-A-600F CLASS ->" at 11108.96,849.13 h60
  text "X" at 12748.02,849.13 h60
  text "2" at 12866.96,849.14 h60
  text "1" at 12551.96,847.64 h60
  text "3" at 13220.96,847.64 h60
  text "X" at 11784.02,689.64 h60
  text "RoHS" at 11920.96,689.64 h60
  text "OTHER" at 12565.36,689.64 h60
  text "PER ORDER" at 12962.42,689.64 h60
  text "ALL BOARDS MUST MEET OR EXCEED UL94-V0 REQUIREMENTS." at 10646,524 h60
  text "PCB MUST BEAR THE UL94V-0 UL REGISTERED MATERIAL ID NUMBER" at 10646,404 h60
  text "ADDITIONAL REQUIREMENTS:" at 10618.46,230.64 h60
  text "MICROSECTION:" at 10693.23,115.64 h60
  text "YES" at 11598.96,115.64 h60
  text "X" at 12920,-40 h60
  text "REQUIRED" at 12460.46,-40.51 h60
  text "BARE BOARD ELEC. TEST:" at 10693.23,-43.36 h60
  text "NONE" at 11998.96,-43.36 h60
  text "PER ORDER" at 13052.46,-43.36 h60
  text ".Layer_Name" at -133,-1868.49 h60
M11 Gerber Information:
  lines w10: -1002,-1940.17 5598,-1940.17 ; -1002,-1736.83 5600,-1736.83 ; -1002,-1533.5 -1002,-2143.5 3003,-2143.5 5600,-2143.5 5600,-1533.5 -1001.5,-1533.5 -1001.5,-2143.5 574,-2143.5 ; 1463,-2143.5 1463,-1533.5 ; 2730,-1736.83 2730,-1533.5 ; 3570,-1736.83 3570,-1533.5 ; 4192,-2150 4192,-1947.17
  text "ALL ARTWORK VIEWED FROM TOP SIDE" at -938.5,-1665.67 h60
  text "BOARD #:" at 1538,-1665.67 h60
  text ".PRJ_Number" at 2083.5,-1665.67 h60
  text "REV:" at 2928,-1665.67 h60
  text ".PCB_Rev" at 3219.5,-1665.67 h60
  text "SVN REV:" at 3766,-1665.67 h60
  text ".VersionControl_RevNumber" at 4272,-1665.67 h60
  text "LAYER NAME =" at -938.5,-1868.49 h60
  text "TID #:" at 1538,-1869 h60
  text ".TID" at 2083.5,-1869 h60
  text "PLOT NAME =" at -938.5,-2074.34 h60
  text ".plot_File_Name" at -133,-2074.34 h60
  text "GENERATED    :" at 1540,-2074.34 h60
  text ".Print_Date" at 2409.5,-2074.34 h60
  text ".Print_Time" at 3138.5,-2074.34 h60
  text "TEXAS INSTRUMENTS" at 4403,-2074.34 h60
M12 Stackup:
  drawing of 295 lines, arcs and shapes, not listed
  text "Layer" at 9080.58,6820 h60
  text "Name" at 9490.49,6820 h60
  text "Material" at 10420.23,6820 h60
  text "Thickness" at 11280,6820 h60
  text "Constant" at 11929.84,6820 h60
  text "Board Layer Stack" at 12499.7,6820 h60
  text "1" at 9080.58,6700 h60
  text "Top Overlay" at 9490.49,6700 h60
  text "2" at 9080.58,6580 h60
  text "Top Solder" at 9490.49,6580 h60
  text "Solder Resist" at 10420.23,6580 h60
  text "0.40mil" at 11280,6580 h60
  text "3.5" at 11929.84,6580 h60
  text "3" at 9080.58,6460 h60
  text "Top Layer" at 9490.49,6460 h60
  text "Copper" at 10420.23,6460 h60
  text "1.40mil" at 11280,6460 h60
  text "4" at 9080.58,6340 h60
  text "Dielectric1" at 9490.49,6340 h60
  text "FR-4" at 10420.23,6340 h60
  text "12.60mil" at 11280,6340 h60
  text "4.2" at 11929.84,6340 h60
  text "5" at 9080.58,6220 h60
  text "Mid-Layer 1" at 9490.49,6220 h60
  text "Copper" at 10420.23,6220 h60
  text "1.40mil" at 11280,6220 h60
  text "6" at 9080.58,6100 h60
  text "Dielectric2" at 9490.49,6100 h60
  text "FR-4" at 10420.23,6100 h60
  text "31.00mil" at 11280,6100 h60
  text "4.2" at 11929.84,6100 h60
  text "7" at 9080.58,5980 h60
  text "Mid-Layer 2" at 9490.49,5980 h60
  text "Copper" at 10420.23,5980 h60
  text "1.40mil" at 11280,5980 h60
  text "8" at 9080.58,5860 h60
  text "Dielectric3" at 9490.49,5860 h60
  text "FR-4" at 10420.23,5860 h60
  text "12.60mil" at 11280,5860 h60
  text "4.2" at 11929.84,5860 h60
  text "9" at 9080.58,5740 h60
  text "Bottom Layer" at 9490.49,5740 h60
  text "Copper" at 10420.23,5740 h60
  text "1.40mil" at 11280,5740 h60
  text "10" at 9080.58,5620 h60
  text "Bottom Solder" at 9490.49,5620 h60
  text "Solder Resist" at 10420.23,5620 h60
  text "0.40mil" at 11280,5620 h60
  text "3.5" at 11929.84,5620 h60
  text "11" at 9080.58,5500 h60
  text "Bottom Overlay" at 9490.49,5500 h60
  text ".Layer_Name" at -133,-1868.49 h60
M13 Component Bodies Top:
  text ".Layer_Name" at -133,-1868.49 h60
M14 Component Bodies Bottom:
  text ".Layer_Name" at -133,-1868.49 h60
M15 Courtyards Top:
  text ".Layer_Name" at -133,-1868.49 h60
M16 Courtyards Bottom:
  text ".Layer_Name" at -133,-1868.49 h60
Drill Drawing:
  circle w3.33: c4862.8,910.83 r24.91
  lines w3.33: 4837.89,151.08 4850.35,151.08 4850.35,138.63 4875.26,138.63 4875.26,151.08 4887.71,151.08 4887.71,175.99 4875.26,175.99 4875.26,188.45 4850.35,188.45 4850.35,175.99 4837.89,175.99 4837.89,151.08 ; 4837.89,288.09 4862.8,300.54 4887.71,288.09 4875.26,313 4887.71,337.91 4862.8,325.45 4837.89,337.91 4850.35,313 4837.89,288.09 ; 4837.89,450 4850.35,450 4862.8,437.54 4875.26,450 4887.71,450 4875.26,462.45 4887.71,474.91 4875.26,474.91 4862.8,487.36 4850.35,474.91 4837.89,474.91 4850.35,462.45 4837.89,450 ; 4837.89,587 4887.71,587 4887.71,636.82 4837.89,636.82 4837.89,587 ; 4837.89,786.28 4887.71,786.28 4862.8,736.46 4837.89,786.28
  lines w12: 4770,93.79 6889.4,93.79 ; 4770,990.54 6889.4,990.54 ; 5140.67,-55.67 5140.67,1140 ; 5497.78,-55.67 5497.78,1140 ; 6159.79,-55.67 6159.79,1140 ; 6444.14,-55.67 6444.14,1140 ; 4770,-55.67 6889.4,-55.67 6889.4,1140 4770,1140 4770,-55.67
  text "Symbol" at 4859.68,1035.38 h72
  text "Quantity" at 5185.51,1035.38 h72
  text "Finished Hole Size" at 5542.62,1035.38 h72
  text "Plated" at 6204.62,1035.38 h72
  text "Hole Type" at 6488.98,1035.38 h72
  text "8" at 5185.51,885.92 h60
  text "15.00mil (0.381mm)" at 5542.62,885.92 h60
  text "PTH" at 6204.62,885.92 h60
  text "Round" at 6488.98,885.92 h60
  text "79" at 5185.51,736.46 h60
  text "28.00mil (0.711mm)" at 5542.62,736.46 h60
  text "PTH" at 6204.62,736.46 h60
  text "Round" at 6488.98,736.46 h60
  text "2" at 5185.51,587 h60
  text "43.31mil (1.100mm)" at 5542.62,587 h60
  text "PTH" at 6204.62,587 h60
  text "Round" at 6488.98,587 h60
  text "3" at 5185.51,437.54 h60
  text "45.00mil (1.143mm)" at 5542.62,437.54 h60
  text "PTH" at 6204.62,437.54 h60
  text "Round" at 6488.98,437.54 h60
  text "10" at 5185.51,288.09 h60
  text "47.24mil (1.200mm)" at 5542.62,288.09 h60
  text "PTH" at 6204.62,288.09 h60
  text "Round" at 6488.98,288.09 h60
  text "2" at 5185.51,138.63 h60
  text "51.18mil (1.300mm)" at 5542.62,138.63 h60
  text "PTH" at 6204.62,138.63 h60
  text "Round" at 6488.98,138.63 h60
  text "104 Total" at 5185.51,-10.83 h60
  text ".Layer_Name" at -133,-1868.49 h60

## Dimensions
-710,-1410 to 290,-1410 on M2 Board Dimensions
0,-10 to 4400,-10 on M2 Board Dimensions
